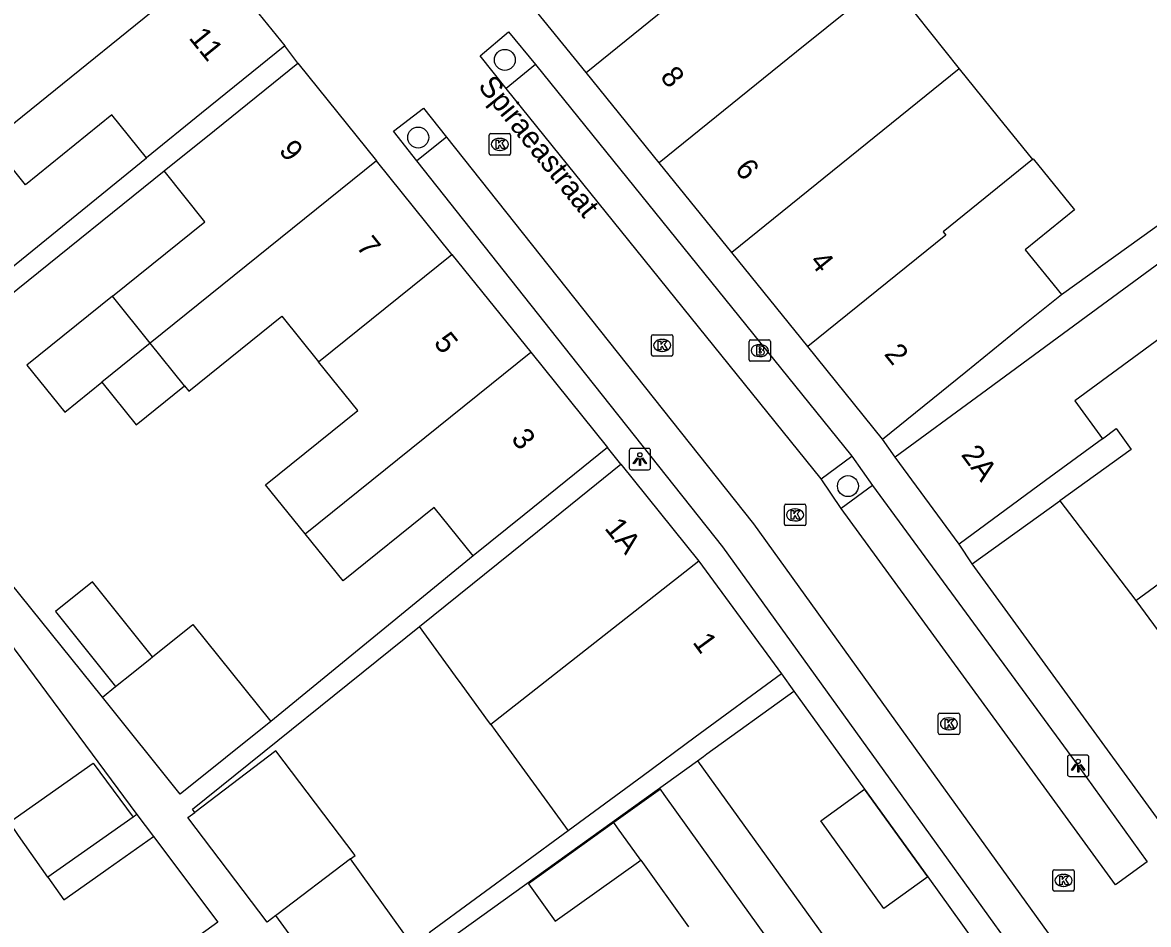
# Model space of a CAD drawing. Extents: x 161882 to 162509, y 381687 to 382379.
# Drawn here: x 162223.5 to 162276, y 381938.8 to 381980.9 of the extents above; entities that cross this region are included whole.
import ezdxf

# ---------------------------------------------------------------- set-up
doc = ezdxf.new("R2010")
doc.units = 0
for name, color, linetype in [('IMGEO_Boom', 7, 'Continuous'), ('IMGEO_Brandkraan', 7, 'Continuous'), ('IMGEO_Kolk', 7, 'Continuous'), ('IMGEO_Lichtpunt', 7, 'Continuous'), ('IMGEO_Muur', 7, 'Continuous'), ('IMGEO_Openbare_ruimte_label', 7, 'Continuous'), ('IMGEO_Pand', 7, 'Continuous'), ('IMGEO_Pand_nummerreeks', 7, 'Continuous'), ('IMGEO_Parkeervlak_open', 7, 'Continuous'), ('IMGEO_Rijbaan_lokaal_open', 7, 'Continuous'), ('IMGEO_Voetpad_open', 7, 'Continuous')]:
    doc.layers.add(name, color=color, linetype=linetype)

msp = doc.modelspace()

# ---------------------------------------------------------------- linework, layer by layer
at = {"layer": 'IMGEO_Boom'}
for centre in [(162246.01, 381979.174), (162241.969, 381975.553), (162262.01, 381959.292)]:
    msp.add_circle(centre, 0.489, dxfattribs=at)
at = {"layer": 'IMGEO_Brandkraan'}
for p, q in [((162257.396, 381965.189), (162257.396, 381966.041)), ((162257.471, 381966.115), (162258.323, 381966.115)), ((162257.884, 381965.895), (162257.909, 381965.895)), ((162258.397, 381966.041), (162258.397, 381965.189)), ((162257.907, 381965.335), (162257.882, 381965.335)), ((162258.323, 381965.115), (162257.471, 381965.115))]:
    msp.add_line(p, q, dxfattribs=at)
for points in [[(162257.396, 381965.189), (162257.396, 381966.041)], [(162257.471, 381966.115), (162258.323, 381966.115)], [(162257.744, 381965.815), (162257.744, 381965.415), (162257.957, 381965.415)], [(162257.975, 381965.815), (162257.744, 381965.815)], [(162258.397, 381966.041), (162258.397, 381965.189)], [(162257.923, 381965.734), (162257.869, 381965.734), (162257.869, 381965.658)], [(162257.869, 381965.658), (162257.922, 381965.658)], [(162257.931, 381965.582), (162257.869, 381965.582), (162257.869, 381965.501)], [(162257.869, 381965.501), (162257.931, 381965.501)], [(162258.323, 381965.115), (162257.471, 381965.115)]]:
    msp.add_lwpolyline(points, dxfattribs=at)
for centre, radius, start, end in [((162257.473, 381966.039), 0.0765, 91.552, 178.448), ((162257.473, 381966.039), 0.0765, 91.552, 178.448), ((162257.979, 381965.67), 0.145, 59.4692, 91.5367), ((162258.321, 381966.039), 0.0765, 1.552, 88.448), ((162258.321, 381966.039), 0.0765, 1.552, 88.448), ((162257.924, 381965.696), 0.0379, 267.8285, 90.9355), ((162257.932, 381965.541), 0.0404, 269.8759, 90.5077), ((162257.963, 381965.666), 0.251, 268.6676, 293.5347), ((162258.004, 381965.717), 0.0922, 285.5137, 58.1501), ((162258.009, 381965.525), 0.105, 301.3115, 78.989), ((162257.473, 381965.191), 0.0765, 181.552, 268.448), ((162257.473, 381965.191), 0.0765, 181.552, 268.448), ((162258.321, 381965.191), 0.0765, 271.552, 358.448), ((162258.321, 381965.191), 0.0765, 271.552, 358.448)]:
    msp.add_arc(centre, radius, start, end, dxfattribs=at)
for centre, major_axis, ratio, start_param, end_param in [((162257.883, 381965.615), (-0.387, 0.002), 0.722429, 4.712389, 7.853982), ((162257.908, 381965.615), (-0.39, 0.002), 0.717154, 1.570796, 4.712389)]:
    msp.add_ellipse(centre, major_axis=major_axis, ratio=ratio, start_param=start_param, end_param=end_param, dxfattribs=at)
at = {"layer": 'IMGEO_Kolk'}
for p, q in [((162245.277, 381974.808), (162245.277, 381975.66)), ((162245.352, 381975.734), (162246.204, 381975.734)), ((162245.765, 381975.514), (162245.79, 381975.514)), ((162246.278, 381975.66), (162246.278, 381974.808)), ((162245.788, 381974.954), (162245.763, 381974.954)), ((162246.204, 381974.734), (162245.352, 381974.734)), ((162252.921, 381966.355), (162253.773, 381966.355)), ((162252.846, 381965.429), (162252.846, 381966.281)), ((162253.334, 381966.135), (162253.359, 381966.135)), ((162253.847, 381966.281), (162253.847, 381965.429)), ((162253.773, 381965.355), (162252.921, 381965.355)), ((162253.357, 381965.575), (162253.332, 381965.575)), ((162259.044, 381957.522), (162259.044, 381958.374)), ((162259.119, 381958.448), (162259.971, 381958.448)), ((162259.532, 381958.228), (162259.557, 381958.228)), ((162260.045, 381958.374), (162260.045, 381957.522)), ((162259.971, 381957.448), (162259.119, 381957.448)), ((162259.555, 381957.668), (162259.53, 381957.668)), ((162266.219, 381947.776), (162266.219, 381948.628)), ((162266.294, 381948.702), (162267.146, 381948.702)), ((162266.707, 381948.482), (162266.732, 381948.482)), ((162267.22, 381948.628), (162267.22, 381947.776)), ((162267.146, 381947.702), (162266.294, 381947.702)), ((162266.73, 381947.922), (162266.705, 381947.922)), ((162271.563, 381940.47), (162271.563, 381941.322)), ((162271.638, 381941.396), (162272.49, 381941.396)), ((162272.051, 381941.176), (162272.076, 381941.176)), ((162272.564, 381941.322), (162272.564, 381940.47)), ((162272.074, 381940.616), (162272.049, 381940.616)), ((162272.49, 381940.396), (162271.638, 381940.396))]:
    msp.add_line(p, q, dxfattribs=at)
for points in [[(162245.277, 381974.808), (162245.277, 381975.66)], [(162245.352, 381975.734), (162246.204, 381975.734)], [(162245.598, 381975.434), (162245.721, 381975.434), (162245.721, 381975.283), (162245.851, 381975.434), (162246.015, 381975.434), (162245.869, 381975.283), (162246.022, 381975.034), (162245.87, 381975.034), (162245.785, 381975.198), (162245.721, 381975.131), (162245.721, 381975.034), (162245.598, 381975.034), (162245.598, 381975.434)], [(162246.278, 381975.66), (162246.278, 381974.808)], [(162246.204, 381974.734), (162245.352, 381974.734)], [(162252.921, 381966.355), (162253.773, 381966.355)], [(162252.846, 381965.429), (162252.846, 381966.281)], [(162253.167, 381966.055), (162253.29, 381966.055), (162253.29, 381965.904), (162253.42, 381966.055), (162253.584, 381966.055), (162253.438, 381965.904), (162253.591, 381965.655), (162253.439, 381965.655), (162253.354, 381965.819), (162253.29, 381965.752), (162253.29, 381965.655), (162253.167, 381965.655), (162253.167, 381966.055)], [(162253.847, 381966.281), (162253.847, 381965.429)], [(162253.773, 381965.355), (162252.921, 381965.355)], [(162259.044, 381957.522), (162259.044, 381958.374)], [(162259.119, 381958.448), (162259.971, 381958.448)], [(162259.365, 381958.148), (162259.488, 381958.148), (162259.488, 381957.997), (162259.618, 381958.148), (162259.782, 381958.148), (162259.636, 381957.997), (162259.789, 381957.748), (162259.637, 381957.748), (162259.552, 381957.912), (162259.488, 381957.845), (162259.488, 381957.748), (162259.365, 381957.748), (162259.365, 381958.148)], [(162260.045, 381958.374), (162260.045, 381957.522)], [(162259.971, 381957.448), (162259.119, 381957.448)], [(162266.219, 381947.776), (162266.219, 381948.628)], [(162266.294, 381948.702), (162267.146, 381948.702)], [(162267.22, 381948.628), (162267.22, 381947.776)], [(162266.54, 381948.402), (162266.663, 381948.402), (162266.663, 381948.251), (162266.793, 381948.402), (162266.957, 381948.402), (162266.811, 381948.251), (162266.964, 381948.002), (162266.812, 381948.002), (162266.727, 381948.166), (162266.663, 381948.099), (162266.663, 381948.002), (162266.54, 381948.002), (162266.54, 381948.402)], [(162267.146, 381947.702), (162266.294, 381947.702)], [(162271.563, 381940.47), (162271.563, 381941.322)], [(162271.638, 381941.396), (162272.49, 381941.396)], [(162272.564, 381941.322), (162272.564, 381940.47)], [(162271.884, 381941.096), (162272.007, 381941.096), (162272.007, 381940.945), (162272.137, 381941.096), (162272.301, 381941.096), (162272.155, 381940.945), (162272.308, 381940.696), (162272.156, 381940.696), (162272.071, 381940.86), (162272.007, 381940.793), (162272.007, 381940.696), (162271.884, 381940.696), (162271.884, 381941.096)], [(162272.49, 381940.396), (162271.638, 381940.396)]]:
    msp.add_lwpolyline(points, dxfattribs=at)
for centre, start, end in [((162245.354, 381975.658), 91.552, 178.448), ((162245.354, 381975.658), 91.552, 178.448), ((162246.202, 381975.658), 1.552, 88.448), ((162246.202, 381975.658), 1.552, 88.448), ((162245.354, 381974.81), 181.552, 268.448), ((162245.354, 381974.81), 181.552, 268.448), ((162246.202, 381974.81), 271.552, 358.448), ((162246.202, 381974.81), 271.552, 358.448), ((162252.923, 381966.279), 91.552, 178.448), ((162252.923, 381966.279), 91.552, 178.448), ((162253.771, 381966.279), 1.552, 88.448), ((162253.771, 381966.279), 1.552, 88.448), ((162252.923, 381965.431), 181.552, 268.448), ((162252.923, 381965.431), 181.552, 268.448), ((162253.771, 381965.431), 271.552, 358.448), ((162253.771, 381965.431), 271.552, 358.448), ((162259.121, 381958.372), 91.552, 178.448), ((162259.121, 381958.372), 91.552, 178.448), ((162259.969, 381958.372), 1.552, 88.448), ((162259.969, 381958.372), 1.552, 88.448), ((162259.121, 381957.524), 181.552, 268.448), ((162259.121, 381957.524), 181.552, 268.448), ((162259.969, 381957.524), 271.552, 358.448), ((162259.969, 381957.524), 271.552, 358.448), ((162266.296, 381948.626), 91.552, 178.448), ((162266.296, 381948.626), 91.552, 178.448), ((162267.144, 381948.626), 1.552, 88.448), ((162267.144, 381948.626), 1.552, 88.448), ((162266.296, 381947.778), 181.552, 268.448), ((162266.296, 381947.778), 181.552, 268.448), ((162267.144, 381947.778), 271.552, 358.448), ((162267.144, 381947.778), 271.552, 358.448), ((162271.64, 381941.32), 91.552, 178.448), ((162271.64, 381941.32), 91.552, 178.448), ((162272.488, 381941.32), 1.552, 88.448), ((162272.488, 381941.32), 1.552, 88.448), ((162271.64, 381940.472), 181.552, 268.448), ((162271.64, 381940.472), 181.552, 268.448), ((162272.488, 381940.472), 271.552, 358.448), ((162272.488, 381940.472), 271.552, 358.448)]:
    msp.add_arc(centre, 0.0765, start, end, dxfattribs=at)
for centre, major_axis, ratio, start_param, end_param in [((162245.764, 381975.234), (-0.387, 0.002), 0.722429, 4.712389, 7.853982), ((162245.789, 381975.234), (-0.39, 0.002), 0.717154, 1.570796, 4.712389), ((162253.333, 381965.855), (-0.387, 0.002), 0.722429, 4.712389, 7.853982), ((162253.358, 381965.855), (-0.39, 0.002), 0.717154, 1.570796, 4.712389), ((162259.531, 381957.948), (-0.387, 0.002), 0.722429, 4.712389, 7.853982), ((162259.556, 381957.948), (-0.39, 0.002), 0.717154, 1.570796, 4.712389), ((162266.706, 381948.202), (-0.387, 0.002), 0.722429, 4.712389, 7.853982), ((162266.731, 381948.202), (-0.39, 0.002), 0.717154, 1.570796, 4.712389), ((162272.05, 381940.896), (-0.387, 0.002), 0.722429, 4.712389, 7.853982), ((162272.075, 381940.896), (-0.39, 0.002), 0.717154, 1.570796, 4.712389)]:
    msp.add_ellipse(centre, major_axis=major_axis, ratio=ratio, start_param=start_param, end_param=end_param, dxfattribs=at)
at = {"layer": 'IMGEO_Lichtpunt'}
for p, q in [((162251.81, 381960.952), (162251.81, 381960.145)), ((162251.81, 381960.952), (162251.81, 381960.145)), ((162252.712, 381961.047), (162251.904, 381961.047)), ((162252.712, 381961.047), (162251.904, 381961.047)), ((162252.806, 381960.145), (162252.806, 381960.952)), ((162252.806, 381960.145), (162252.806, 381960.952)), ((162251.904, 381960.051), (162252.712, 381960.051)), ((162251.904, 381960.051), (162252.712, 381960.051)), ((162272.247, 381946.648), (162272.247, 381945.841)), ((162272.247, 381946.648), (162272.247, 381945.841)), ((162273.149, 381946.743), (162272.341, 381946.743)), ((162273.149, 381946.743), (162272.341, 381946.743)), ((162273.243, 381945.841), (162273.243, 381946.648)), ((162273.243, 381945.841), (162273.243, 381946.648)), ((162272.341, 381945.747), (162273.149, 381945.747)), ((162272.341, 381945.747), (162273.149, 381945.747))]:
    msp.add_line(p, q, dxfattribs=at)
for points in [[(162252.184, 381960.616), (162252.223, 381960.588), (162252.035, 381960.326), (162251.997, 381960.353), (162252.184, 381960.616)], [(162252.286, 381960.568), (162252.333, 381960.568), (162252.333, 381960.246), (162252.286, 381960.246), (162252.286, 381960.568)], [(162252.396, 381960.588), (162252.434, 381960.615), (162252.621, 381960.353), (162252.582, 381960.325), (162252.396, 381960.588)], [(162272.621, 381946.312), (162272.66, 381946.284), (162272.472, 381946.022), (162272.434, 381946.049), (162272.621, 381946.312)], [(162272.723, 381946.264), (162272.77, 381946.264), (162272.77, 381945.942), (162272.723, 381945.942), (162272.723, 381946.264)], [(162272.833, 381946.284), (162272.871, 381946.311), (162273.058, 381946.049), (162273.019, 381946.021), (162272.833, 381946.284)]]:
    msp.add_lwpolyline(points, dxfattribs=at)
for centre in [(162252.309, 381960.75), (162272.746, 381946.446)]:
    msp.add_circle(centre, 0.0994, dxfattribs=at)
for centre, start, end in [((162251.904, 381960.952), 90, 180), ((162251.904, 381960.952), 90, 180), ((162252.712, 381960.952), 0, 90), ((162252.712, 381960.952), 0, 90), ((162251.904, 381960.145), 180, 270), ((162251.904, 381960.145), 180, 270), ((162252.712, 381960.145), 270, 0), ((162252.712, 381960.145), 270, 360), ((162272.341, 381946.648), 90, 180), ((162272.341, 381946.648), 90, 180), ((162273.149, 381946.648), 0, 90), ((162273.149, 381946.648), 0, 90), ((162272.341, 381945.841), 180, 270), ((162272.341, 381945.841), 180, 270), ((162273.149, 381945.841), 270, 0), ((162273.149, 381945.841), 270, 360)]:
    msp.add_arc(centre, 0.0946, start, end, dxfattribs=at)
at = {"layer": 'IMGEO_Muur'}
msp.add_lwpolyline([(162265.743, 381941.056), (162262.789, 381945.152)], dxfattribs=at)
at = {"layer": 'IMGEO_Pand'}
for points in [[(162249.797, 381978.591), (162260.442, 381987.195)], [(162232.515, 381983.832), (162222.035, 381975.349)], [(162232.515, 381983.832), (162235.753, 381979.827)], [(162249.797, 381978.591), (162246.202, 381983.039)], [(162263.853, 381982.975), (162259.611, 381979.545), (162253.208, 381974.369)], [(162263.853, 381982.975), (162267.194, 381978.758)], [(162235.753, 381979.827), (162231.866, 381976.683), (162229.303, 381974.61)], [(162230.119, 381973.992), (162232.464, 381975.881), (162236.357, 381979.017)], [(162236.357, 381979.017), (162240.026, 381974.462)], [(162253.208, 381974.369), (162249.797, 381978.591)], [(162267.194, 381978.758), (162256.588, 381970.186)], [(162267.194, 381978.758), (162269.022, 381976.495), (162270.613, 381974.526)], [(162229.303, 381974.61), (162227.687, 381976.607), (162223.654, 381973.346), (162222.035, 381975.349)], [(162240.026, 381974.462), (162229.472, 381965.955)], [(162243.536, 381970.103), (162240.026, 381974.462)], [(162256.588, 381970.186), (162253.208, 381974.369)], [(162270.613, 381974.526), (162266.443, 381971.157), (162266.571, 381970.998), (162260.135, 381965.797)], [(162270.613, 381974.526), (162270.65, 381974.556), (162272.57, 381972.179), (162270.27, 381970.32), (162271.962, 381968.227)], [(162227.706, 381968.148), (162232.024, 381971.626), (162230.119, 381973.992)], [(162237.319, 381965.092), (162243.536, 381970.103)], [(162243.536, 381970.103), (162247.216, 381965.535)], [(162260.135, 381965.797), (162256.588, 381970.186)], [(162277.105, 381970.115), (162273.118, 381967.183), (162268.244, 381963.598), (162264.216, 381960.635)], [(162277.105, 381970.115), (162278.433, 381968.312), (162278.79, 381967.827), (162277.375, 381966.786), (162277.103, 381966.586), (162272.583, 381963.262), (162273.876, 381961.504)], [(162227.706, 381968.148), (162223.721, 381964.938), (162225.488, 381962.744), (162227.217, 381964.137)], [(162229.472, 381965.955), (162227.706, 381968.148)], [(162263.619, 381961.485), (162267.509, 381964.628), (162270.032, 381966.667), (162271.962, 381968.227)], [(162231.075, 381963.964), (162231.271, 381963.721), (162235.609, 381967.215), (162237.319, 381965.092)], [(162229.472, 381965.955), (162227.217, 381964.137)], [(162231.075, 381963.964), (162229.472, 381965.955)], [(162236.702, 381957.062), (162247.216, 381965.535)], [(162247.216, 381965.535), (162250.799, 381961.086)], [(162263.619, 381961.485), (162260.135, 381965.797)], [(162236.702, 381957.062), (162234.856, 381959.354), (162239.153, 381962.815), (162237.319, 381965.092)], [(162227.217, 381964.137), (162228.82, 381962.146), (162231.075, 381963.964)], [(162250.799, 381961.086), (162246.905, 381957.95), (162244.529, 381956.036)], [(162273.876, 381961.504), (162271.221, 381959.551), (162267.193, 381956.588)], [(162267.193, 381956.588), (162264.216, 381960.635)], [(162242.03, 381952.743), (162247.531, 381957.173), (162251.425, 381960.309)], [(162251.425, 381960.309), (162255.061, 381955.795)], [(162267.802, 381955.667), (162271.892, 381958.607)], [(162271.892, 381958.607), (162275.442, 381953.947)], [(162244.529, 381956.036), (162242.713, 381958.291), (162238.467, 381954.871), (162236.702, 381957.062)], [(162255.061, 381955.795), (162245.352, 381948.172)], [(162255.061, 381955.795), (162258.907, 381950.535)], [(162279.505, 381940.876), (162278.431, 381941.04), (162267.802, 381955.667)], [(162275.442, 381953.947), (162277.413, 381955.397), (162280.63, 381951.023), (162282.568, 381952.448)], [(162229.585, 381951.326), (162226.78, 381954.827), (162225.053, 381953.435), (162227.858, 381949.935)], [(162275.442, 381953.947), (162283.109, 381943.527)], [(162229.585, 381951.326), (162231.463, 381952.84), (162235.093, 381948.309)], [(162245.352, 381948.172), (162245.249, 381948.313), (162244.023, 381950), (162243.712, 381950.427), (162242.03, 381952.743)], [(162227.858, 381949.935), (162228.677, 381950.595), (162229.477, 381951.239), (162229.585, 381951.326)], [(162258.907, 381950.535), (162254.881, 381947.571), (162252.408, 381945.751), (162248.956, 381943.21)], [(162227.249, 381949.444), (162227.858, 381949.935)], [(162254.989, 381946.479), (162255.271, 381946.682), (162255.435, 381946.801), (162259.49, 381949.726)], [(162259.49, 381949.726), (162262.789, 381945.152)], [(162235.093, 381948.309), (162230.869, 381944.925), (162227.249, 381949.444)], [(162245.352, 381948.172), (162245.562, 381947.882), (162248.956, 381943.21)], [(162238.819, 381941.9), (162239.032, 381942.062), (162235.328, 381946.94), (162231.548, 381944.07)], [(162254.989, 381946.479), (162261.684, 381937.198)], [(162224.7, 381941.042), (162223.336, 381942.994), (162222.907, 381943.607), (162226.816, 381946.365), (162228.677, 381943.848)], [(162261.684, 381937.198), (162259.887, 381935.909), (162256.749, 381940.287), (162253.438, 381944.906), (162253.266, 381945.147), (162251.089, 381943.595)], [(162265.743, 381941.056), (162263.687, 381939.582), (162260.749, 381943.681), (162262.789, 381945.152)], [(162228.677, 381943.848), (162224.7, 381941.042)], [(162228.855, 381943.973), (162228.677, 381943.848)], [(162228.855, 381943.973), (162229.626, 381942.938)], [(162235.338, 381939.256), (162234.933, 381938.949), (162231.228, 381943.827), (162231.548, 381944.07)], [(162251.089, 381943.595), (162247.106, 381940.741), (162248.363, 381938.987), (162252.346, 381941.841)], [(162252.346, 381941.841), (162251.265, 381943.349), (162251.089, 381943.595)], [(162224.7, 381941.042), (162225.439, 381939.984), (162226.925, 381941.032), (162227.518, 381941.451), (162229.626, 381942.938)], [(162238.819, 381941.9), (162235.384, 381939.291), (162235.338, 381939.256)], [(162242.214, 381937.16), (162241.883, 381937.622), (162241.73, 381937.835), (162238.819, 381941.9)], [(162252.346, 381941.841), (162254.576, 381938.73)], [(162265.743, 381941.056), (162270.07, 381935.019), (162269.88, 381933.866)], [(162238.663, 381934.615), (162236.228, 381938.014), (162235.951, 381938.401), (162235.338, 381939.256)]]:
    msp.add_lwpolyline(points, dxfattribs=at)
at = {"layer": 'IMGEO_Parkeervlak_open'}
for points in [[(162247.432, 381978.966), (162246.074, 381977.838)], [(162243.291, 381975.571), (162241.902, 381974.46)], [(162260.754, 381959.631), (162262.184, 381960.692)], [(162263.159, 381959.315), (162261.693, 381958.246)]]:
    msp.add_lwpolyline(points, dxfattribs=at)
at = {"layer": 'IMGEO_Rijbaan_lokaal_open'}
for points in [[(162246.074, 381977.838), (162244.861, 381979.365), (162246.175, 381980.481), (162247.432, 381978.966)], [(162236.357, 381979.017), (162235.753, 381979.827)], [(162247.432, 381978.966), (162262.184, 381960.692)], [(162260.754, 381959.631), (162246.074, 381977.838)], [(162241.902, 381974.46), (162240.825, 381975.85), (162242.214, 381976.929), (162243.291, 381975.571)], [(162243.291, 381975.571), (162250.83, 381966.065), (162257.599, 381957.53), (162265.697, 381946.277), (162271.344, 381938.429), (162269.9, 381937.391), (162264.255, 381945.235), (162256.181, 381956.455), (162249.437, 381964.96), (162241.902, 381974.46)], [(162251.425, 381960.309), (162250.799, 381961.086)], [(162264.216, 381960.635), (162263.619, 381961.485)], [(162262.184, 381960.692), (162263.159, 381959.315)], [(162261.693, 381958.246), (162260.754, 381959.631)], [(162263.159, 381959.315), (162272.74, 381946.245), (162275.957, 381941.764), (162274.491, 381940.695), (162269.077, 381948.12), (162261.693, 381958.246)], [(162267.802, 381955.667), (162267.193, 381956.588)], [(162258.907, 381950.535), (162259.49, 381949.726)], [(162262.789, 381945.152), (162265.743, 381941.056)]]:
    msp.add_lwpolyline(points, dxfattribs=at)
at = {"layer": 'IMGEO_Voetpad_open'}
for points in [[(162271.962, 381968.227), (162284.816, 381977.446), (162283.991, 381978.635)], [(162219.296, 381966.478), (162229.303, 381974.61)], [(162216.458, 381962.987), (162230.119, 381973.992)], [(162227.249, 381949.444), (162217.209, 381961.9), (162216.458, 381962.987)], [(162273.876, 381961.504), (162274.515, 381961.973), (162275.217, 381960.997), (162271.892, 381958.607)], [(162206.259, 381951.071), (162217.446, 381959.364), (162228.855, 381943.973)], [(162244.529, 381956.036), (162235.093, 381948.309)], [(162231.548, 381944.07), (162231.438, 381944.215), (162242.03, 381952.743)], [(162248.956, 381943.21), (162242.479, 381938.444), (162242.946, 381937.81), (162254.989, 381946.479)], [(162229.626, 381942.938), (162232.631, 381938.95), (162219.25, 381929.308)]]:
    msp.add_lwpolyline(points, dxfattribs=at)

# ---------------------------------------------------------------- texts
at = {"layer": 'IMGEO_Openbare_ruimte_label'}
msp.add_text('Spiraeastraat', height=1, rotation=308.8298, dxfattribs=at).set_placement((162244.722, 381977.937))
at = {"layer": 'IMGEO_Pand_nummerreeks'}
for s, rotation, p in [('11', 308.9579, (162231.239, 381980.194)), ('8', 308.938, (162253.217, 381978.368)), ('9', 308.8487, (162235.436, 381974.933)), ('6', 308.938, (162256.698, 381974.061)), ('7', 308.8463, (162239.046, 381970.45)), ('4', 308.938, (162260.182, 381969.75)), ('5', 308.8487, (162242.657, 381965.967)), ('2', 308.938, (162263.664, 381965.44)), ('3', 308.8487, (162246.267, 381961.484)), ('2A', 306.3368, (162267.258, 381960.752)), ('1A', 308.8521, (162250.625, 381957.317)), ('1', 306.1706, (162254.736, 381952.004))]:
    msp.add_text(s, height=1, rotation=rotation, dxfattribs=at).set_placement(p)

doc.saveas('drawing.dxf')
